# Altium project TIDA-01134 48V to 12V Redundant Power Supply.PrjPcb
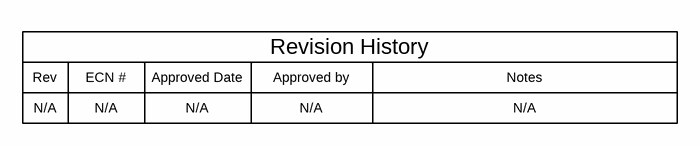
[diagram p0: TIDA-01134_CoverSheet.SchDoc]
CopyrightYear: 2016; PCB_Layout: X. Gong; PCB_Rev: E1; PRJ_Customer: Public Release; PRJ_Engineer: X. Gong; PRJ_Number: TIDA-01344; PRJ_Title: Automotive Ultra Wide Vin 48V Battery to 12V, 1.7A Fly-back Reference Design; SCH_Rev: E1; TechSupport: http://www.ti.com/support; TID: 1344
4 sheets, 91 parts. Net scope: global (net labels, ports and power ports of the same name join across sheets).
Board file: TIDA-01134_PCB.PcbDoc
Sheets:
  TIDA-01134_CoverSheet.SchDoc
  TIDA-01134_FlyBack_Converter.SchDoc
  TIDA-01134_Protection_EMI_Filter.SchDoc
  TIDA-01134_Hardware.SchDoc

## Sheet TIDA-01134_CoverSheet.SchDoc: Block Diagram
size 431 x 279 mm; VersionControl_RevNumber: E1; Date: Not shown in title block; ApprovedBy: Not shown in title block; CheckedBy: Not shown in title block; Author: Not shown in title block; CompanyName: Not shown in title block; DrawnBy: X. Gong; Engineer: Not shown in title block; Organization: Not shown in title block; Address1: Not shown in title block; Address2: Not shown in title block; Address3: Not shown in title block; Address4: Not shown in title block; DocumentNumber: 1; Revision: Use project parameter SCH_Rev; SheetNumber: 1; SheetTotal: 4; PageSetup: Record=PageOptions¦CenterHorizontal=True¦CenterVertical=True¦PrintScale=1.00¦XCorrection=1.00¦YCorrection=1.00¦PrintKind=0¦BorderSize=5000000¦LeftOffset=0¦BottomOffset=0¦Orientation=2¦PaperLength=1000¦PaperWidth=1000¦Scale=100¦PaperSource=15¦PrintQuality=600¦MediaType=1¦DitherType=10¦PaperKind=Letter¦PrintScaleMode=1

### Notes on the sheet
- Rev
- N/A
- ECN #
- Approved Date
- Approved by
- Revision History
- Notes

## Sheet TIDA-01134_FlyBack_Converter.SchDoc: FlyBack Converter
size 431 x 279 mm; VersionControl_RevNumber: E1; Date: Not shown in title block; ApprovedBy: Not shown in title block; CheckedBy: Not shown in title block; Author: Not shown in title block; CompanyName: Not shown in title block; DrawnBy: X. Gong; Engineer: Not shown in title block; Organization: Not shown in title block; Address1: Not shown in title block; Address2: Not shown in title block; Address3: Not shown in title block; Address4: Not shown in title block; DocumentNumber: 2; Revision: Use project parameter SCH_Rev; SheetNumber: 2; SheetTotal: 4; PageSetup: Record=PageOptions¦CenterHorizontal=True¦CenterVertical=True¦PrintScale=1.00¦XCorrection=1.00¦YCorrection=1.00¦PrintKind=0¦BorderSize=5000000¦LeftOffset=0¦BottomOffset=0¦Orientation=2¦PaperLength=1000¦PaperWidth=1000¦Scale=100¦PaperSource=15¦PrintQuality=600¦MediaType=1¦DitherType=10¦PaperKind=Letter¦PrintScaleMode=1
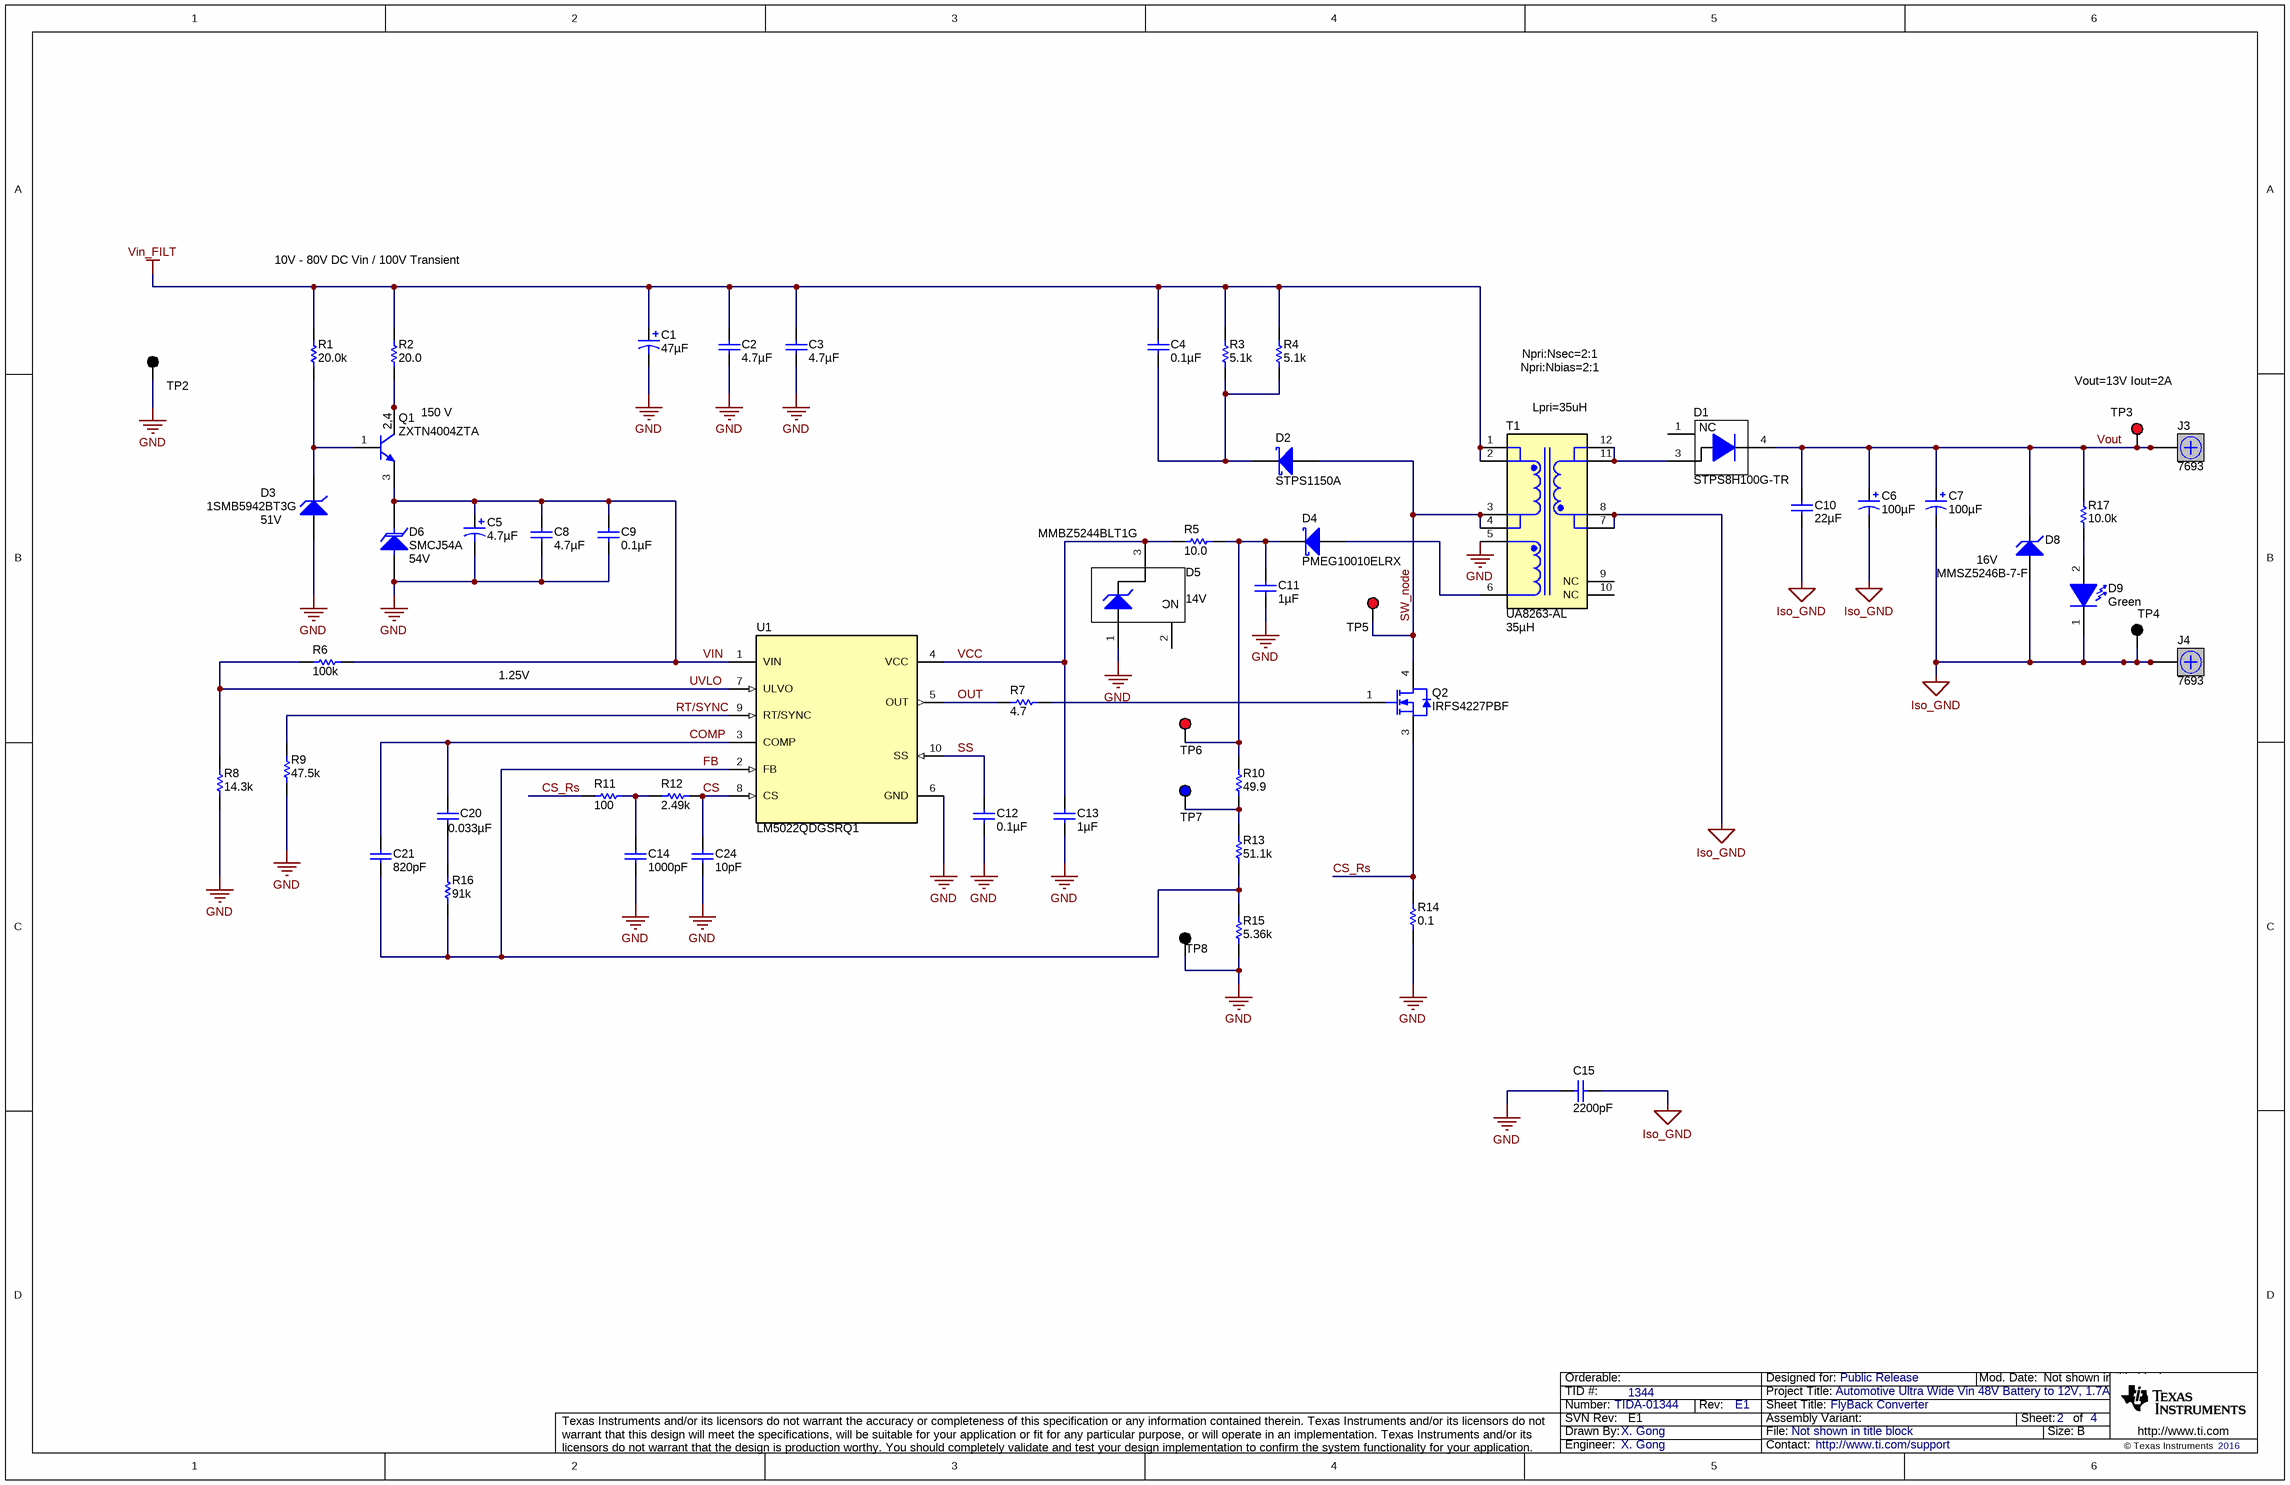
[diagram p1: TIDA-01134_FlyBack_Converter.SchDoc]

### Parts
C1  ValueDisplayed: 47µF  [SM_RADIAL_H13]  (hidden comment: EEV-FK2A470Q)
C2  ValueDisplayed: 4.7µF  [1210_220]  (hidden comment: GRM32DC72A475KE01L)
C3  ValueDisplayed: 4.7µF  [1210_220]  (hidden comment: GRM32DC72A475KE01L)
C4  ValueDisplayed: 0.1µF  [0805_HV]  (hidden comment: CGA4J2X7R2A104K125AA)
C5  ValueDisplayed: 4.7µF  [SM_RADIAL_D]  (hidden comment: EEE-FK1K4R7P)
C6  ValueDisplayed: 100µF  [SM_RADIAL_D8]  (hidden comment: EEE-FK1E101XP)
C7  ValueDisplayed: 100µF  [SM_RADIAL_D8]  (hidden comment: EEE-FK1E101XP)
C8  ValueDisplayed: 4.7µF  [1210_220]  (hidden comment: GRM32DC72A475KE01L)
C9  ValueDisplayed: 0.1µF  [1206]  (hidden comment: GRM319R72A104KA01D)
C10  ValueDisplayed: 22µF  [1210_270]  (hidden comment: GRM32ER71E226KE15L)
C11  ValueDisplayed: 1µF  [0805_HV]  (hidden comment: GRM216R61E105KA12D)
C12  ValueDisplayed: 0.1µF  [0603]  (hidden comment: GRM188R71H104KA93D)
C13  ValueDisplayed: 1µF  [0805_HV]  (hidden comment: GRM216R61E105KA12D)
C14  ValueDisplayed: 1000pF  [0805_HV]  (hidden comment: GCM2165C1H102JA16D)
C15  ValueDisplayed: 2200pF  [CAPRD1000W60D900H1200]  (hidden comment: DE1E3KX222MA4BL01)
C20  ValueDisplayed: 0.033µF  [0805_HV]  (hidden comment: GRM219R71H333KA01D)
C21  ValueDisplayed: 820pF  [0805_HV]  (hidden comment: GRM2165C1H821JA01D)
C24  ValueDisplayed: 10pF  [0603]  (hidden comment: GRM1885C1H100JA01D)
D1  STPS8H100G-TR  [DDPAK]
D2  STPS1150A  [SMA]
D3  1SMB5942BT3G  value 51V  [SMB]
D4  PMEG10010ELRX  [SOD-123W]
D5  MMBZ5244BLT1G  value 14V  [SOT-23]
D6  SMCJ54A  value 54V  [SMC]
D8  MMSZ5246B-7-F  value 16V  [SOD-123]
D9  value Green  [WL-SMCW_GREEN]  (hidden comment: 150060GS75000)
J3  7693  [7693]
J4  7693  [7693]
Q1  ZXTN4004ZTA  value 150 V  [SOT-89-3]
Q2  IRFS4227PBF  [DDPAK]
R1  ValueDisplayed: 20.0k  [2512]  (hidden comment: CRCW251220K0FKEG)
R2  ValueDisplayed: 20.0  [2512]  (hidden comment: CRCW251220R0FKEG)
R3  ValueDisplayed: 5.1k  [2010]  (hidden comment: CRCW20105K10JNEF)
R4  ValueDisplayed: 5.1k  [2010]  (hidden comment: CRCW20105K10JNEF)
R5  ValueDisplayed: 10.0  [0603]  (hidden comment: CRCW060310R0FKEA)
R6  ValueDisplayed: 100k  [0805_HV]  (hidden comment: CRCW0805100KFKEA)
R7  ValueDisplayed: 4.7  [0603]  (hidden comment: CRCW06034R70JNEA)
R8  ValueDisplayed: 14.3k  [0805_HV]  (hidden comment: CRCW080514K3FKEA)
R9  ValueDisplayed: 47.5k  [0603]  (hidden comment: CRCW060347K5FKEA)
R10  ValueDisplayed: 49.9  [0603]  (hidden comment: CRCW060349R9FKEA)
R11  ValueDisplayed: 100  [0805_HV]  (hidden comment: CRCW0805100RFKEA)
R12  ValueDisplayed: 2.49k  [0805_HV]  (hidden comment: CRCW08052K49FKEA)
R13  ValueDisplayed: 51.1k  [0603]  (hidden comment: CRCW060351K1FKEA)
R14  ValueDisplayed: 0.1  [2512]  (hidden comment: CRM2512-FX-R100ELF)
R15  ValueDisplayed: 5.36k  [0603]  (hidden comment: CRCW06035K36FKEA)
R16  ValueDisplayed: 91k  [0805_HV]  (hidden comment: CRCW080591K0JNEA)
R17  ValueDisplayed: 10.0k  [0603]  (hidden comment: CRCW060310K0FKEA)
T1  UA8263-AL  ValueDisplayed: 35µH  [Coilcraft_UA8263-AL]
TP2  5006  [Keystone5006]  (value not drawn)
TP3  5005  [Keystone5005]  (value not drawn)
TP4  5006  [Keystone5006]  (value not drawn)
TP5  5005  [Keystone5005]  (value not drawn)
TP6  5005  [Keystone5005]  (value not drawn)
TP7  5122  [Keystone5122]  (value not drawn)
TP8  5006  [Keystone5006]  (value not drawn)
U1  LM5022QDGSRQ1  [DGS0010A_N]

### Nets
GND: C1.2(-) C2.2 C3.2 C5.2(-) C8.2 C9.2 C11.2 C12.2 C13.2 C14.2 C15.2 C24.2 D3.2(A) D5.1(A) D6.2(A) R8.1 R9.1 R14.1 R15.1 T1.5 TP2.1 TP8.1 U1.6(GND)
Iso_GND: C6.2(-) C7.2(-) C10.2 C15.1 D8.2(A) D9.1(K) J4.1 J4.2 J4.3 J4.4 T1.7 T1.8 TP4.1
Vin_FILT: C1.1(+) C2.1 C3.1 C4.1 R1.2 R2.2 R3.2 R4.2 T1.1 T1.2
COMP: C20.1 C21.1 U1.3(COMP)
CS: C24.1 R12.2 U1.8(CS)
CS_Rs: Q2.3(S) R11.1 R14.2
FB: C21.2 R13.1 R15.2 R16.1 U1.2(FB)
OUT: R7.1 U1.5(OUT)
RT/SYNC: R9.2 U1.9(RT/SYNC)
SS: C12.1 U1.10(SS)
SW_node: D2.2(A) Q2.4(D) T1.3 T1.4 TP5.1
UVLO: R6.1 R8.2 U1.7(ULVO)
VCC: C13.1 D5.3(K) R5.1 U1.4(VCC)
VIN: C5.1(+) C8.1 C9.1 D6.1(K) Q1.3(E) R6.2 U1.1(VIN)
Vout: C6.1(+) C7.1(+) C10.1 D1.4(K) D8.1(K) J3.1 J3.2 J3.3 J3.4 R17.2 TP3.1
NetC4_2: C4.2 D2.1(K) R3.1 R4.1
NetC11_1: C11.1 D4.1(K) R5.2 R10.2 TP6.1
NetC14_1: C14.1 R11.2 R12.1
NetC20_2: C20.2 R16.2
NetD1_3: D1.3(A) T1.11 T1.12
NetD3_1: D3.1(K) Q1.1(B) R1.1
NetD4_2: D4.2(A) T1.6
NetD9_2: D9.2(A) R17.1
NetQ1_2: Q1.2(C) Q1.4(C) R2.1
NetQ2_1: Q2.1(G) R7.2
NetR10_1: R10.1 R13.2 TP7.1

Not connected (* = marked no-connect by the designer): D1 1(NC); D5 2(NC); T1 9(NC) 10(NC)

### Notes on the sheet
- 10V - 80V DC Vin / 100V Transient
- Npri:Nsec=2:1
- Npri:Nbias=2:1
- (near T1) Lpri=35uH
- Vout=13V Iout=2A
- 1.25V

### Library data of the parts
C1 = EEV-FK2A470Q: CAP, AL, 47 µF, 100 V, +/- 20%, 0.32 ohm, AEC-Q200 Grade 2, SMD; Manufacturer: Panasonic; Polarized: Y; CompType: Capacitor; Value: 47uF; U/M: EA; Cap_F: 0.000047; Tolerance_%: 20; VDC_V: 100; Value2: 100V; ESR_ohm: 0.32; IRMS_A: 0.5; TaMin_C: -55; TaMax_C: 105; Cap_Case: H13; SizeAreaWB_mm2: 263.5; SizeArea_mm2: 202.5; SizeX_mm: 15; SizeY_mm: 13.5; AEC Category: Q200; AEC Grade: 2
C2 C3 C8 = GRM32DC72A475KE01L: CAP, CERM, 4.7 µF, 100 V, +/- 10%, X7S, 1210; Manufacturer: MuRata; Polarized: N; CompType: Capacitor; Value: 4.7uF; U/M: EA; Cap_F: 0.0000047; Tolerance_%: 10; Value1: Unknown; VDC_V: 100; Value2: 100V; TaMin_C: -55; TaMax_C: 125; Cap_Case: 1210; SizeArea_mm2: 8; SizeAreaWB_mm2: 14.7; SizeX_mm: 3.2; SizeY_mm: 2.5; SizeZ_mm: 2.2; AEC Category: Q200
C4 = CGA4J2X7R2A104K125AA: CAP, CERM, 0.1 µF, 100 V, +/- 10%, X7R, AEC-Q200 Grade 1, 0805; Manufacturer: TDK; Polarized: N; CompType: Capacitor; Value: 0.1uF; U/M: EA; Cap_F: 0.0000001; Tolerance_%: 10; ESR_ohm: 0.020726; Value1: 0.020726 ohm; VDC_V: 100; Value2: 100V; IRMS_A: 1.456; TaMin_C: -55; TaMax_C: 125; Cap_Case: 0805; SizeArea_mm2: 2.5; SizeAreaWB_mm2: 6.75; SizeX_mm: 2; SizeY_mm: 1.25; SizeZ_mm: 1.45; AEC Category: Q200; AEC Qualified: Y; AEC Grade: 1
C5 = EEE-FK1K4R7P: CAP, AL, 4.7 µF, 80 V, +/- 20%, 3 ohm, AEC-Q200 Grade 2, SMD; Manufacturer: Panasonic; Polarized: Y; CompType: Capacitor; Value: 4.7uF; U/M: EA; Cap_F: 0.0000047; Tolerance_%: 20; Value1: 3 ohm; VDC_V: 80; Value2: 80V; ESR_ohm: 3; IRMS_A: 0.04; TaMin_C: -55; TaMax_C: 105; Cap_Case: D; SizeAreaWB_mm2: 84.28; SizeArea_mm2: 51.48; SizeX_mm: 7.8; SizeY_mm: 6.6; SizeZ_mm: 5.4; AEC Category: Q200; AEC Grade: 2
C6 C7 = EEE-FK1E101XP: CAP, AL, 100 µF, 25 V, +/- 20%, 0.34 ohm, AEC-Q200 Grade 2, SMD; Manufacturer: Panasonic; Polarized: Y; CompType: Capacitor; Value: 100uF; U/M: EA; Cap_F: 0.0001; Tolerance_%: 20; VDC_V: 25; Value2: 25V; ESR_ohm: 0.34; IRMS_A: 0.28; TaMin_C: -55; TaMax_C: 105; Cap_Case: D8; SizeAreaWB_mm2: 84.28; SizeArea_mm2: 51.48; SizeX_mm: 7.8; SizeY_mm: 6.6; SizeZ_mm: 7.7; AEC Category: Q200; AEC Grade: 2
C9 = GRM319R72A104KA01D: CAP, CERM, 0.1 µF, 100 V, +/- 10%, X7R, 1206; Manufacturer: MuRata; Polarized: N; CompType: Capacitor; Value: 0.1uF; U/M: EA; Cap_F: 0.0000001; Tolerance_%: 10; Value1: Unknown; VDC_V: 100; Value2: 100V; TaMin_C: -55; TaMax_C: 125; SizeArea_mm2: 5.12; SizeAreaWB_mm2: 10.92; SizeX_mm: 3.2; SizeY_mm: 1.6; SizeZ_mm: 1.35; AEC Category: Q200
C10 = GRM32ER71E226KE15L: CAP, CERM, 22 µF, 25 V, +/- 10%, X7R, 1210; Manufacturer: MuRata; Polarized: N; CompType: Capacitor; Value: 22uF; U/M: EA; Cap_F: 0.000022; Tolerance_%: 10; Value1: Unknown; VDC_V: 25; Value2: 25V; TaMin_C: -55; TaMax_C: 125; Cap_Case: 1210; SizeArea_mm2: 8; SizeAreaWB_mm2: 14.7; SizeX_mm: 3.2; SizeY_mm: 2.5; SizeZ_mm: 2.7; AEC Category: Q200
C11 C13 = GRM216R61E105KA12D: CAP, CERM, 1 µF, 25 V, +/- 10%, X5R, 0805; Manufacturer: MuRata; Polarized: N; CompType: Capacitor; Value: 1uF; U/M: EA; Cap_F: 0.000001; Tolerance_%: 10; ESR_ohm: 0.009; Value1: 0.009 ohm; VDC_V: 25; Value2: 25V; TaMin_C: -55; TaMax_C: 85; Cap_Case: 0805; SizeArea_mm2: 2.5; SizeAreaWB_mm2: 6.75; SizeX_mm: 2; SizeY_mm: 1.25; SizeZ_mm: 1.45; AEC Category: Q200
C12 = GRM188R71H104KA93D: CAP, CERM, 0.1 µF, 50 V, +/- 10%, X7R, 0603; Manufacturer: MuRata; Polarized: N; CompType: Capacitor; Value: 0.1uF; U/M: EA; Cap_F: 0.0000001; Tolerance_%: 10; Value1: Unknown; VDC_V: 50; Value2: 50V; TaMin_C: -55; TaMax_C: 125; SizeArea_mm2: 1.28; SizeAreaWB_mm2: 4.68; SizeX_mm: 1.6; SizeY_mm: 0.8; SizeZ_mm: 1; AEC Category: Q200
C14 = GCM2165C1H102JA16D: CAP, CERM, 1000 pF, 50 V, +/- 5%, C0G/NP0, AEC-Q200 Grade 1, 0805; Manufacturer: MuRata; Polarized: N; CompType: Capacitor; Value: 1000pF; U/M: EA; Cap_F: 0.000000001; Tolerance_%: 5; Value1: Unknown; VDC_V: 50; Value2: 50V; TaMin_C: -55; TaMax_C: 125; Cap_Case: 0805; SizeArea_mm2: 2.5; SizeAreaWB_mm2: 6.75; SizeX_mm: 2; SizeY_mm: 1.25; SizeZ_mm: 1.45; AEC Category: Q200; AEC Qualified: Y; AEC Grade: 1
C15 = DE1E3KX222MA4BL01: CAP, CERM, 2200 pF, 250 V, +/- 20%, E, Cap, 7x12x9 mm; Manufacturer: MuRata; Polarized: N; CompType: Capacitor; Value: 2200pF; U/M: EA; Cap_F: 0.0000000022; Tolerance_%: 20; Value1: Unknown; VDC_V: 250; Value2: 250V; TaMin_C: -25; TaMax_C: 85; SizeArea_mm2: 80.5; SizeAreaWB_mm2: 121.5; SizeX_mm: 11.5; SizeY_mm: 7; SizeZ_mm: 12.5; AEC Category: Q200
C20 = GRM219R71H333KA01D: CAP, CERM, 0.033 µF, 50 V, +/- 10%, X7R, 0805; Manufacturer: MuRata; Polarized: N; CompType: Capacitor; Value: 0.033uF; U/M: EA; Cap_F: 0.000000033; Tolerance_%: 10; Value1: Unknown; VDC_V: 50; Value2: 50V; TaMin_C: -55; TaMax_C: 125; Cap_Case: 0805; SizeArea_mm2: 2.5; SizeAreaWB_mm2: 6.75; SizeX_mm: 2; SizeY_mm: 1.25; SizeZ_mm: 1.45; AEC Category: Q200
C21 = GRM2165C1H821JA01D: CAP, CERM, 820 pF, 50 V, +/- 5%, C0G/NP0, 0805; Manufacturer: MuRata; Polarized: N; CompType: Capacitor; Value: 820pF; U/M: EA; Cap_F: 0.00000000082; Tolerance_%: 5; Value1: Unknown; VDC_V: 50; Value2: 50V; TaMin_C: -55; TaMax_C: 125; Cap_Case: 0805; SizeArea_mm2: 2.5; SizeAreaWB_mm2: 6.75; SizeX_mm: 2; SizeY_mm: 1.25; SizeZ_mm: 1.45; AEC Category: Q200
C24 = GRM1885C1H100JA01D: CAP, CERM, 10 pF, 50 V, +/- 5%, C0G/NP0, 0603; Manufacturer: MuRata; Polarized: N; CompType: Capacitor; Value: 10pF; U/M: EA; Cap_F: 0.00000000001; Tolerance_%: 5; Value1: Unknown; VDC_V: 50; Value2: 50V; TaMin_C: -55; TaMax_C: 125; SizeArea_mm2: 1.28; SizeAreaWB_mm2: 4.68; SizeX_mm: 1.6; SizeY_mm: 0.8; SizeZ_mm: 1; AEC Category: Q200
D1 = STPS8H100G-TR: Diode, Schottky, 100 V, 8 A, DDPAK; Manufacturer: STMicroelectronics; SymbolCreator: a0412235; U/M: EA; Vf_V: 0.71; Value: 100V; Value1: 8A; Value2: 0.71V; Io_A: 8; Vr_V: 100; TJmax_C: 175; RJC_CperW: 1.6; SizeAreaWB_mm2: 209.6992; SizeArea_mm2: 154.8892; SizeX_mm: 15.245; SizeY_mm: 10.16; SizeZ_mm: 4.445; AEC Category: Q101; AEC Qualified: N
D2 = STPS1150A: Diode, Schottky, 150 V, 1 A, SMA; Manufacturer: STMicroelectronics; U/M: EA; Vf_V: 0.78; Value: 150V; Value1: 1A; Value2: 0.78V; Io_A: 1; Vr_V: 150; TJmax_C: 175; RJC_CperW: 30; SizeAreaWB_mm2: 37.3428; SizeArea_mm2: 16.3228; SizeX_mm: 5.59; SizeY_mm: 2.92; SizeZ_mm: 2.87; AEC Category: Q101; AEC Qualified: N
D3 = 1SMB5942BT3G: Diode, Zener, 51 V, 550 mW, SMB; Manufacturer: ON Semiconductor; SymbolCreator: a0412235; U/M: EA; Power_W: 0.55; Vz_V: 51; Value1: 0.55W; RJA_CperW: 226; SizeAreaWB_mm2: 44.156; SizeArea_mm2: 21.336; SizeX_mm: 5.6; SizeY_mm: 3.81; SizeZ_mm: 2.6; AEC Category: Q101
D4 = PMEG10010ELRX: Diode, Schottky, 100 V, 1 A, AEC-Q101, SOD-123W; Manufacturer: NXP Semiconductor; U/M: EA; Vf_V: 0.77; Value: 100V; Value1: 1A; Value2: 0.77V; Io_A: 1; Vr_V: 100; TJmax_C: 175; SizeAreaWB_mm2: 12.15; SizeArea_mm2: 5.95; SizeX_mm: 3.5; SizeY_mm: 1.7; AEC Category: Q101; AEC Qualified: Y
D5 = MMBZ5244BLT1G: Diode, Zener, 14 V, 225 mW, SOT-23; Manufacturer: ON Semiconductor; U/M: EA; Power_W: 0.225; Vz_V: 14; Value1: 0.225W; RJA_CperW: 556; SizeArea_mm2: 7.5; SizeX_mm: 2.5; SizeY_mm: 3; SizeZ_mm: 1.1; AEC Category: Q101
D6 = SMCJ54A: Diode, TVS, Uni, 54 V, SMC; Manufacturer: Fairchild Semiconductor; U/M: EA; Vr_V: 54; Value1: W; SizeAreaWB_mm2: 83.2686; SizeArea_mm2: 50.5686; SizeX_mm: 8.13; SizeY_mm: 6.22; SizeZ_mm: 2.6; AEC Category: Q101
D8 = MMSZ5246B-7-F: Diode, Zener, 16 V, 500 mW, SOD-123; Manufacturer: Diodes Inc.; SymbolCreator: a0412235; U/M: EA; Power_W: 0.5; Vz_V: 16; Value1: 0.5W; RJA_CperW: 350; SizeAreaWB_mm2: 13.095; SizeArea_mm2: 6.545; SizeX_mm: 3.85; SizeY_mm: 1.7; SizeZ_mm: 1.35; AEC Category: Q101
D9 = 150060GS75000: LED, Green, SMD; Manufacturer: Wurth Elektronik; Type: InGaN; Vf_V: 3.2; Value2: 3.2V; Io_A: 0.02; Tjmax_C: 85; Value1: W; Angle: 140; U/M: EA
J3 J4 = 7693: Terminal screw, vertical, snap-in; Manufacturer: Keystone; SymbolCreator: a0412235; CompType: Screw Terminal
Q1 = ZXTN4004ZTA, Diodes Inc.: Transistor, NPN, 150 V, 1 A, SOT-89; SymbolCreator: a0412235; PNP: 0; NPN: 1; Vceo_V: 150; Value1: 1 A; TaMin_C: -55; CompType: BJT; U/M: EA; AEC Category: Q101
Q2 = IRFS4227PBF: MOSFET, N-CH, 200 V, 62 A, DDPAK; Manufacturer: International Rectifier; Alternate Manufacturer: None; U/M: EA; ChType: N; Value: 200V; VdsMax_V: 200; Value1: ? ohm; Value2: 70 nC; QgTyp_nC: 70; Vgs_V: 30; IdsMax_A: 62; SizeAreaWB_mm2: 209.6992; SizeArea_mm2: 154.8892; SizeX_mm: 15.245; SizeY_mm: 10.16; SizeZ_mm: 4.445; AEC Category: Q101
R1 = CRCW251220K0FKEG: RES, 20.0 k, 1%, 1 W, AEC-Q200 Grade 0, 2512; Manufacturer: Vishay-Dale; CompType: Resistor; Value: 20.0k; Res_ohm: 20000; Value_Code: 20k0; Tolerance_%: 1; Value2: 1W; VDC_V: 500; TempCo: 100 ppm/C; SizeArea_mm2: 20.16; SizeX_mm: 6.3; SizeY_mm: 3.2; SizeZ_mm: 0.71; EIA_Code: E96; U/M: EA; AEC Category: Q200; AEC Qualified: Y; AEC Grade: 0
R2 = CRCW251220R0FKEG: RES, 20.0, 1%, 1 W, AEC-Q200 Grade 0, 2512; Manufacturer: Vishay-Dale; CompType: Resistor; Value: 20.0; Res_ohm: 20; Value_Code: 20R0; Tolerance_%: 1; Value2: 1W; VDC_V: 500; TempCo: 100 ppm/C; SizeArea_mm2: 20.16; SizeX_mm: 6.3; SizeY_mm: 3.2; SizeZ_mm: 0.71; EIA_Code: E96; U/M: EA; AEC Category: Q200; AEC Qualified: Y; AEC Grade: 0
R3 R4 = CRCW20105K10JNEF: RES, 5.1 k, 5%, 0.75 W, AEC-Q200 Grade 0, 2010; Manufacturer: Vishay-Dale; CompType: Resistor; Value: 5.1k; Res_ohm: 5100; Value_Code: 5k10; Tolerance_%: 5; Power_W: 0.75; Value2: 0.75W; VDC_V: 400; TempCo: 200 ppm/C; SizeArea_mm2: 12.5; SizeY_mm: 2.5; SizeZ_mm: 1.66; EIA_Code: E24; U/M: EA; AEC Category: Q200; AEC Qualified: Y; AEC Grade: 0
R5 = CRCW060310R0FKEA: RES, 10.0, 1%, 0.1 W, 0603; Manufacturer: Vishay-Dale; CompType: Resistor; Value: 10.0; Res_ohm: 10; Value_Code: 10R0; Tolerance_%: 1; Power_W: 0.1; Value2: 0.1W; VDC_V: 75; TempCo: 100 ppm/C; SizeArea_mm2: 1.28; SizeX_mm: 1.6; SizeY_mm: 0.8; EIA_Code: E96; U/M: EA; AEC Category: Q200
R6 = CRCW0805100KFKEA: RES, 100 k, 1%, 0.125 W, 0805; Manufacturer: Vishay-Dale; CompType: Resistor; Value: 100k; Res_ohm: 100000; Tolerance_%: 1; Power_W: 0.125; Value2: 0.125W; VDC_V: 150; TempCo: 100 ppm/C; SizeArea_mm2: 2.5; SizeX_mm: 2; SizeY_mm: 1.25; SizeZ_mm: 1.45; EIA_Code: E96; U/M: EA; AEC Category: Q200
R7 = CRCW06034R70JNEA: RES, 4.7, 5%, 0.1 W, 0603; Manufacturer: Vishay-Dale; CompType: Resistor; Value: 4.7; Value_Code: 4R70; Tolerance_%: 5; Power_W: 0.1; Value2: 0.1W; VDC_V: 75; TempCo: 200 ppm/C; SizeArea_mm2: 1.28; SizeX_mm: 1.6; SizeY_mm: 0.8; SizeZ_mm: 1; EIA_Code: E24; U/M: EA; AEC Category: Q200
R8 = CRCW080514K3FKEA: RES, 14.3 k, 1%, 0.125 W, 0805; Manufacturer: Vishay-Dale; CompType: Resistor; Value: 14.3k; Res_ohm: 14300; Value_Code: 14k3; Tolerance_%: 1; Power_W: 0.125; Value2: 0.125W; VDC_V: 150; TempCo: 100 ppm/C; SizeArea_mm2: 2.5; SizeX_mm: 2; SizeY_mm: 1.25; SizeZ_mm: 1.45; EIA_Code: E96; U/M: EA; AEC Category: Q200
R9 = CRCW060347K5FKEA: RES, 47.5 k, 1%, 0.1 W, 0603; Manufacturer: Vishay-Dale; CompType: Resistor; Value: 47.5k; Res_ohm: 47500; Value_Code: 47k5; Tolerance_%: 1; Power_W: 0.1; Value2: 0.1W; VDC_V: 75; TempCo: 100 ppm/C; SizeArea_mm2: 1.28; SizeX_mm: 1.6; SizeY_mm: 0.8; EIA_Code: E96; U/M: EA; AEC Category: Q200
R10 = CRCW060349R9FKEA: RES, 49.9, 1%, 0.1 W, 0603; Manufacturer: Vishay-Dale; CompType: Resistor; Value: 49.9; Value_Code: 49R9; Tolerance_%: 1; Power_W: 0.1; Value2: 0.1W; VDC_V: 75; TempCo: 100 ppm/C; SizeArea_mm2: 1.28; SizeX_mm: 1.6; SizeY_mm: 0.8; EIA_Code: E96; U/M: EA; AEC Category: Q200
R11 = CRCW0805100RFKEA: RES, 100, 1%, 0.125 W, 0805; Manufacturer: Vishay-Dale; CompType: Resistor; Value: 100; Value_Code: 100R; Tolerance_%: 1; Power_W: 0.125; Value2: 0.125W; VDC_V: 150; TempCo: 100 ppm/C; SizeArea_mm2: 2.5; SizeX_mm: 2; SizeY_mm: 1.25; SizeZ_mm: 1.45; EIA_Code: E96; U/M: EA; AEC Category: Q200
R12 = CRCW08052K49FKEA: RES, 2.49 k, 1%, 0.125 W, 0805; Manufacturer: Vishay-Dale; CompType: Resistor; Value: 2.49k; Res_ohm: 2490; Value_Code: 2k49; Tolerance_%: 1; Power_W: 0.125; Value2: 0.125W; VDC_V: 150; TempCo: 100 ppm/C; SizeArea_mm2: 2.5; SizeX_mm: 2; SizeY_mm: 1.25; SizeZ_mm: 1.45; EIA_Code: E96; U/M: EA; AEC Category: Q200
R13 = CRCW060351K1FKEA: RES, 51.1 k, 1%, 0.1 W, 0603; Manufacturer: Vishay-Dale; CompType: Resistor; Value: 51.1k; Res_ohm: 51100; Value_Code: 51k1; Tolerance_%: 1; Power_W: 0.1; Value2: 0.1W; VDC_V: 75; TempCo: 100 ppm/C; SizeArea_mm2: 1.28; SizeX_mm: 1.6; SizeY_mm: 0.8; EIA_Code: E96; U/M: EA; AEC Category: Q200
R14 = CRM2512-FX-R100ELF: RES, 0.1, 1%, 2 W, 2512; Manufacturer: Bourns; CompType: Resistor; Value: 0.1; Value_Code: R100; Tolerance_%: 1; Power_W: 2; Value2: 2W; TempCo: 100 ppm/C; SizeArea_mm2: 20.16; SizeX_mm: 6.3; SizeY_mm: 3.2; SizeZ_mm: 0.71; EIA_Code: E96; U/M: EA; AEC Category: Q200; AEC Qualified: N
R15 = CRCW06035K36FKEA: RES, 5.36 k, 1%, 0.1 W, 0603; Manufacturer: Vishay-Dale; CompType: Resistor; Value: 5.36k; Res_ohm: 5360; Value_Code: 5k36; Tolerance_%: 1; Power_W: 0.1; Value2: 0.1W; VDC_V: 75; TempCo: 100 ppm/C; SizeArea_mm2: 1.28; SizeX_mm: 1.6; SizeY_mm: 0.8; EIA_Code: E96; U/M: EA; AEC Category: Q200
R16 = CRCW080591K0JNEA: RES, 91 k, 5%, 0.125 W, 0805; Manufacturer: Vishay-Dale; CompType: Resistor; Value: 91k; Res_ohm: 91000; Value_Code: 91k0; Tolerance_%: 5; Power_W: 0.125; Value2: 0.125W; VDC_V: 150; TempCo: 200 ppm/C; SizeArea_mm2: 2.5; SizeX_mm: 2; SizeY_mm: 1.25; SizeZ_mm: 1.45; EIA_Code: E24; U/M: EA; AEC Category: Q200
R17 = CRCW060310K0FKEA: RES, 10.0 k, 1%, 0.1 W, 0603; Manufacturer: Vishay-Dale; CompType: Resistor; Value: 10.0k; Res_ohm: 10000; Value_Code: 10k0; Tolerance_%: 1; Power_W: 0.1; Value2: 0.1W; VDC_V: 75; TempCo: 100 ppm/C; SizeArea_mm2: 1.28; SizeX_mm: 1.6; SizeY_mm: 0.8; EIA_Code: E96; U/M: EA; AEC Category: Q200
T1 = UA8263-AL: Transformer, Flyback, EFD25, 35 uH, SMT; Manufacturer: Coilcraft; SymbolCreator: Altium; Value: 35uH; Lp: 35; DCR_ohm: 0.01; LeakageL: 0.17; Rs1: 0.009; SizeAreaWB_mm2: 1043.3375; SizeArea_mm2: 917.2575; SizeX_mm: 34.29; SizeY_mm: 26.75; SizeZ_mm: 13.6
TP2 TP4 TP8 = 5006: Test Point, Compact, Black, TH; Manufacturer: Keystone; CompType: Test Point Loop; ContactFinish: Silver
TP3 TP5 TP6 = 5005: Test Point, Compact, Red, TH; Manufacturer: Keystone; CompType: Test Point Loop; ContactFinish: Silver
TP7 = 5122: Test Point, Compact, Blue, TH; Manufacturer: Keystone; CompType: Test Point Loop; U/M: EA; ContactFinish: Silver
U1 = LM5022QDGSRQ1: 2.2MHz 60-V Low Side Controller for Boost, SEPIC and Flyback, DGS0010A (VSSOP-10); Alternate PartNumber: LM5022QDGSTQ1; Manufacturer: Texas Instruments; SymbolCreator: a0411947; SizeArea_mm2: 14.7; SizeAreaWB_mm2: 23.6; SizeX_mm: 4.9; SizeY_mm: 3; SizeZ_mm: 1.1; CompType: IC; U/M: EA

## Sheet TIDA-01134_Protection_EMI_Filter.SchDoc: Protection and EMI Filter
size 431 x 279 mm; VersionControl_RevNumber: E1; Date: Not shown in title block; ApprovedBy: Not shown in title block; CheckedBy: Not shown in title block; Author: Not shown in title block; CompanyName: Not shown in title block; DrawnBy: X. Gong; Engineer: Not shown in title block; Organization: Not shown in title block; Address1: Not shown in title block; Address2: Not shown in title block; Address3: Not shown in title block; Address4: Not shown in title block; DocumentNumber: 3; Revision: Use project parameter SCH_Rev; SheetNumber: 3; SheetTotal: 4; PageSetup: Record=PageOptions¦CenterHorizontal=True¦CenterVertical=True¦PrintScale=1.00¦XCorrection=1.00¦YCorrection=1.00¦PrintKind=0¦BorderSize=5000000¦LeftOffset=0¦BottomOffset=0¦Orientation=2¦PaperLength=1000¦PaperWidth=1000¦Scale=100¦PaperSource=15¦PrintQuality=600¦MediaType=1¦DitherType=10¦PaperKind=Letter¦PrintScaleMode=1
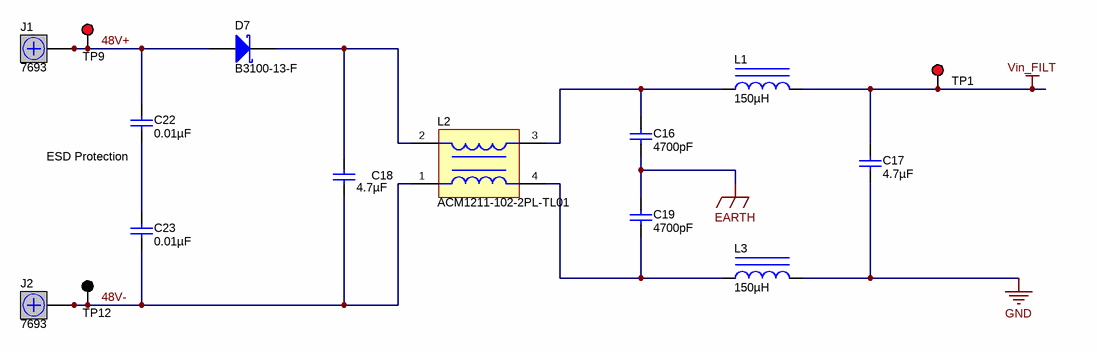
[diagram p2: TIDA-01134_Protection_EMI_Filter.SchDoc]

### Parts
C16  ValueDisplayed: 4700pF  [VY2_1250x500x1650]  (hidden comment: VY2472M49Y5US63V7)
C17  ValueDisplayed: 4.7µF  [1210_220]  (hidden comment: GRM32DC72A475KE01L)
C18  ValueDisplayed: 4.7µF  [1210_220]  (hidden comment: GRM32DC72A475KE01L)
C19  ValueDisplayed: 4700pF  [VY2_1250x500x1650]  (hidden comment: VY2472M49Y5US63V7)
C22  ValueDisplayed: 0.01µF  [1812]  (hidden comment: VJ1812Y103KXEAT5Z)
C23  ValueDisplayed: 0.01µF  [1812]  (hidden comment: VJ1812Y103KXEAT5Z)
D7  B3100-13-F  [SMC]
J1  7693  [7693]
J2  7693  [7693]
L1  ValueDisplayed: 150µH  [MSS1583]  (hidden comment: MSS1583-154KEB)
L2  ACM1211-102-2PL-TL01  [TDK_ACM1211]
L3  ValueDisplayed: 150µH  [MSS1583]  (hidden comment: MSS1583-154KEB)
TP1  5005  [Keystone5005]  (value not drawn)
TP9  5005  [Keystone5005]  (value not drawn)
TP12  5006  [Keystone5006]  (value not drawn)

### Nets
EARTH: C16.2 C19.1
GND: C17.2 L3.2
Vin_FILT: C17.1 L1.2 TP1.1
48V+: C22.1 D7.2(A) J1.1 J1.2 J1.3 J1.4 TP9.1
48V-: C18.2 C23.2 J2.1 J2.2 J2.3 J2.4 L2.1 TP12.1
NetC16_1: C16.1 L1.1 L2.3
NetC18_1: C18.1 D7.1(K) L2.2
NetC19_2: C19.2 L2.4 L3.1
NetC22_2: C22.2 C23.1

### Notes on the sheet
- (near C22) ESD Protection

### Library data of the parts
C16 C19 = VY2472M49Y5US63V7: CAP, CERM, 4700 pF, 440 V, +/- 20%, Y5U, TH, 12.5x5mm; Manufacturer: Vishay-Bccomponents; Polarized: N; CompType: Capacitor; Value: 4700pF; U/M: EA; Cap_F: 0.0000000047; Tolerance_%: 20; Value1: Unknown; VDC_V: 440; Value2: 440V; TaMin_C: -40; TaMax_C: 125; Cap_Case: 12.5x5x16.5; SizeArea_mm2: 62.5; SizeAreaWB_mm2: 101.5; SizeX_mm: 12.5; SizeY_mm: 5; SizeZ_mm: 17.5; AEC Category: Q200
C17 C18 = GRM32DC72A475KE01L: as C2 on sheet TIDA-01134_FlyBack_Converter
C22 C23 = VJ1812Y103KXEAT5Z: CAP, CERM, 0.01 µF, 500 V, +/- 10%, X7R, 1812; Manufacturer: Vishay-Vitramon; Polarized: N; CompType: Capacitor; Value: 0.01uF; U/M: EA; Cap_F: 0.00000001; Tolerance_%: 10; Value1: Unknown; VDC_V: 500; Value2: 500V; TaMin_C: -55; TaMax_C: 125; SizeArea_mm2: 14.4; SizeAreaWB_mm2: 23.1; SizeX_mm: 4.5; SizeY_mm: 3.2; SizeZ_mm: 1.35; AEC Category: Q200
D7 = B3100-13-F: Diode, Schottky, 100 V, 3 A, SMC; Manufacturer: Diodes Inc.; U/M: EA; Vf_V: 0.79; Value: 100V; Value1: 3A; Value2: 0.79V; Io_A: 3; Vr_V: 100; TJmax_C: 125; RJC_CperW: 10; SizeAreaWB_mm2: 83.2686; SizeArea_mm2: 50.5686; SizeX_mm: 8.13; SizeY_mm: 6.22; SizeZ_mm: 2.6; AEC Category: Q101
J1 J2 = 7693: as J3 on sheet TIDA-01134_FlyBack_Converter
L1 L3 = MSS1583-154KEB: Inductor, Drum Core, Ferrite, 150 µH, 2.2 A, 0.138 ohm, SMD; Manufacturer: Coilcraft; Value: 150uH; Ind_H: 150.0E-6; Imax_A: 2.2; Irms: 2.2A @ 40C rise; Isat: 3.9A @ 30% inductance drop; DCR_ohm: 0.138; Value2: 2.2A; SizeAreaWB_mm2: 292.41; SizeArea_mm2: 228.01; SizeX_mm: 15.1; SizeZ_mm: 8.6; AEC Category: Q200; AEC Qualified: N
L2 = ACM1211-102-2PL-TL01: Coupled inductor, 6 A, 0.014 ohm, SMD; Manufacturer: TDK; SymbolCreator: Altium; DCR_ohm: 0.014
TP1 TP9 = 5005: as TP3 on sheet TIDA-01134_FlyBack_Converter
TP12 = 5006: as TP2 on sheet TIDA-01134_FlyBack_Converter

## Sheet TIDA-01134_Hardware.SchDoc: Hardware
size 431 x 279 mm; VersionControl_RevNumber: E1; Date: Not shown in title block; ApprovedBy: Not shown in title block; CheckedBy: Not shown in title block; Author: Not shown in title block; CompanyName: Not shown in title block; DrawnBy: X. Gong; Engineer: Not shown in title block; Organization: Not shown in title block; Address1: Not shown in title block; Address2: Not shown in title block; Address3: Not shown in title block; Address4: Not shown in title block; DocumentNumber: 4; Revision: Use project parameter SCH_Rev; SheetNumber: 4; SheetTotal: 4; PageSetup: Record=PageOptions¦CenterHorizontal=True¦CenterVertical=True¦PrintScale=1.00¦XCorrection=1.00¦YCorrection=1.00¦PrintKind=0¦BorderSize=5000000¦LeftOffset=0¦BottomOffset=0¦Orientation=2¦PaperLength=1000¦PaperWidth=1000¦Scale=100¦PaperSource=15¦PrintQuality=600¦MediaType=1¦DitherType=10¦PaperKind=Letter¦PrintScaleMode=1
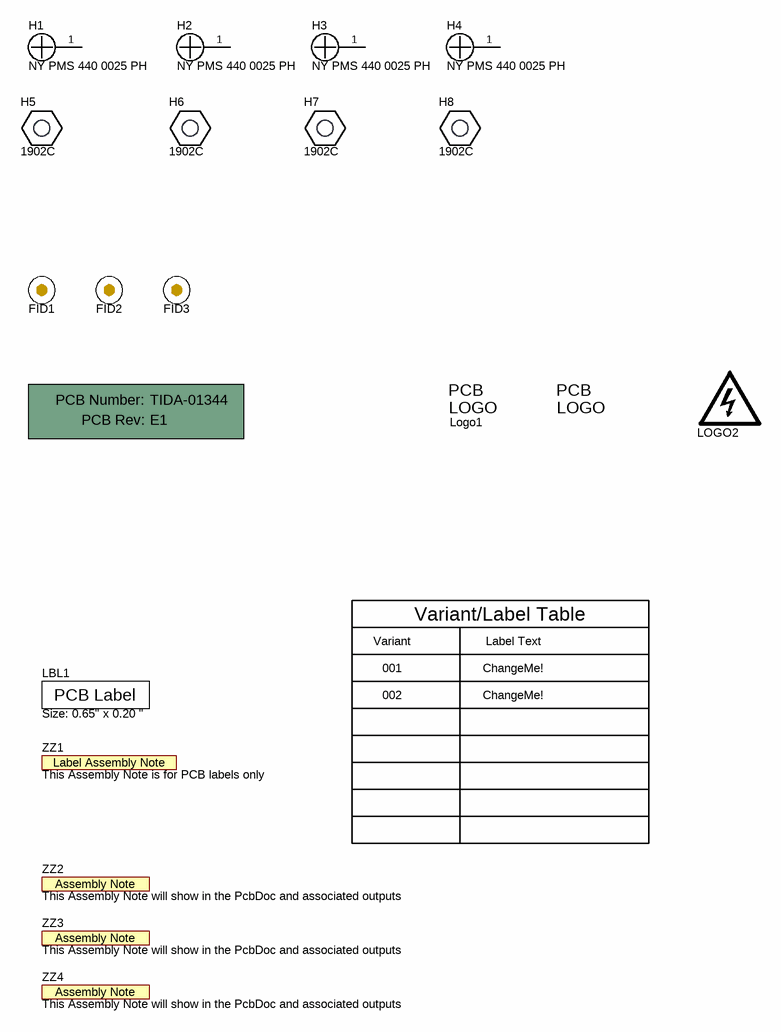
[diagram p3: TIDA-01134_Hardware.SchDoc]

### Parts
!PCB  Printed Circuit Board  (value not drawn)  (mechanical)
FID1  Fiducial  [Fiducial10-20]  (value not drawn)
FID2  Fiducial  [Fiducial10-20]  (value not drawn)
FID3  Fiducial  [Fiducial10-20]  (value not drawn)
H1  NY PMS 440 0025 PH  [NY PMS 440 0025 PH]
H2  NY PMS 440 0025 PH  [NY PMS 440 0025 PH]
H3  NY PMS 440 0025 PH  [NY PMS 440 0025 PH]
H4  NY PMS 440 0025 PH  [NY PMS 440 0025 PH]
H5  1902C  [Keystone_1902C]
H6  1902C  [Keystone_1902C]
H7  1902C  [Keystone_1902C]
H8  1902C  [Keystone_1902C]
LBL1  Size: 0.65" x 0.20 "  [Label_650x200]
Logo1  EU RoHS Exempt Logo  [EURoHS_Exempt_60mil]  (value not drawn)  (no BOM)
LOGO2  DANGER HIGH VOLTAGE  [IEC_HighVoltage_Small]  (value not drawn)  (no BOM)
Logo3  FCC disclaimer  [FCC_disclaimer]  (value not drawn)  (no BOM)
ZZ1  This Assembly Note is for PCB labels only  [AssemblyNoteLabel]  (no BOM)
ZZ2  This Assembly Note will show in the PcbDoc and associated outputs  [AssemblyNote]  (no BOM)
ZZ3  This Assembly Note will show in the PcbDoc and associated outputs  [AssemblyNote]  (no BOM)
ZZ4  This Assembly Note will show in the PcbDoc and associated outputs  [AssemblyNote]  (no BOM)

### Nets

Not connected (* = marked no-connect by the designer): H1 1; H2 1; H3 1; H4 1

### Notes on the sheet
- Variant
- Variant/Label Table
- Label Text
- 001
- 002
- ChangeMe!

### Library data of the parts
!PCB = PCB: Manufacturer: Any; PartNumber: TIDA-01344; SymbolCreator: a0412235
FID1-FID3 = Fiducial: Fiducial mark.  There is nothing to buy or mount.; SymbolCreator: codlsc
H1-H4 = NY PMS 440 0025 PH: Machine Screw, Round, #4-40 x 1/4, Nylon, Philips panhead; Manufacturer: B&F Fastener Supply; CompType: Hardware; SymbolCreator: codlsc; U/M: EA
H5-H8 = 1902C: Standoff, Hex, 0.5"L #4-40 Nylon; Manufacturer: Keystone; CompType: Hardware; SymbolCreator: a0412235
LBL1 = THT-14-423-10: Thermal Transfer Printable Labels, 0.650" W x 0.200" H - 10,000 per roll; Manufacturer: Brady; SymbolCreator: a0412235; CompType: Label
Logo1 = EURoHS_Exempt: SymbolCreator: a0412235
LOGO2 = IEC_HighVoltage: IEC 61010-1 High Voltage Warning; SymbolCreator: a0412235
Logo3 = FCC_disclaimer: SymbolCreator: a0412235
ZZ1 = AssemblyNoteLabel: SymbolCreator: a0412235
ZZ2-ZZ4 = AssemblyNote: SymbolCreator: codlsc

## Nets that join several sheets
GND: TIDA-01134_FlyBack_Converter (23 pins), TIDA-01134_Protection_EMI_Filter (C17.2 L3.2)
Vin_FILT: TIDA-01134_FlyBack_Converter (10 pins), TIDA-01134_Protection_EMI_Filter (C17.1 L1.2 TP1.1)

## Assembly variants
001: not fitted C24 FID1 FID2 FID3 R17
